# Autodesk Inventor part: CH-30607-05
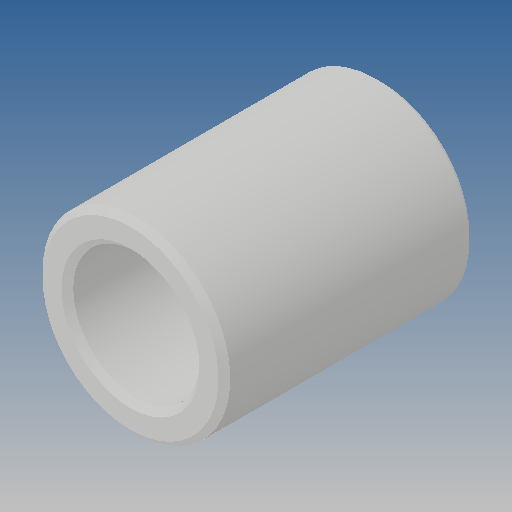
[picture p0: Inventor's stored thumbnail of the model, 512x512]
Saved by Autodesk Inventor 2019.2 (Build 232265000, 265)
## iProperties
Created: 2012-09
Part Number: CH-30607-05
Material: Ogólny
Document SubType Name: Modeling
Designer: CADENGINEERING4
Density: 1 g/cm^3
Appearance: Domyślna
Author: CADENGINEERING4
Revision Number: ÈÎºÎ
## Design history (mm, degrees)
feature "µ¹½Ç1"
node "Bryła1"
